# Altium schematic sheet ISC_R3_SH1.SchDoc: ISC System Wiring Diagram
size B; DrawnBy: Filiberto Clara; Engineer: Filiberto Clara; Organization: LIGO Laboratory; Address1: California Institute of Technology; Address2: Massachusetts Institute of Technology; SheetNumber: 17; SheetTotal: 39
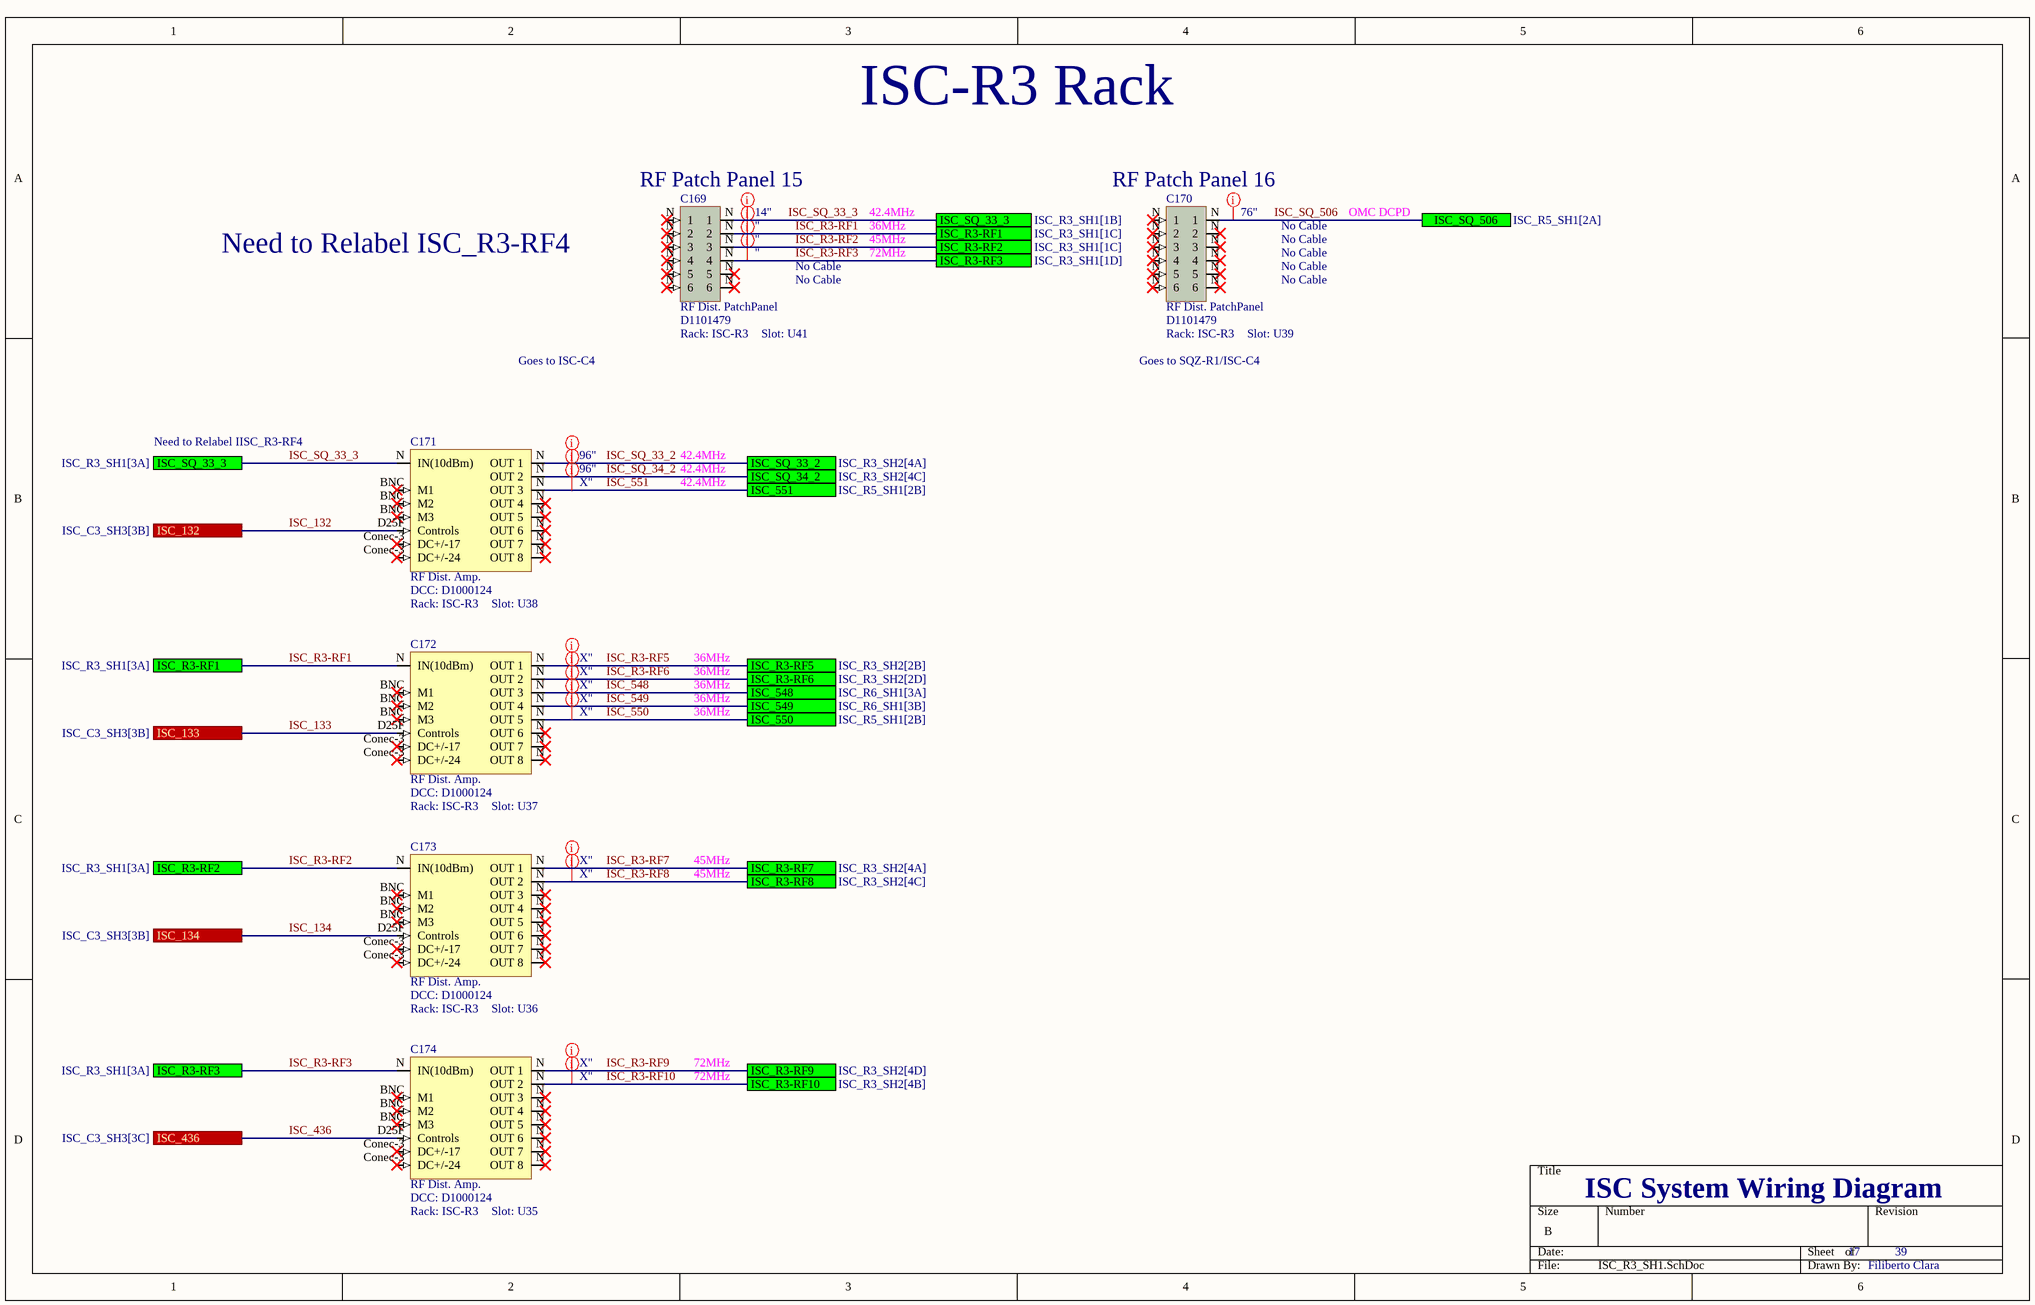
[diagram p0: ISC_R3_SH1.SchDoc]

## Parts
C169  RF Dist. PatchPanel  DCC: D1101479  Rack: ISC-R3  Slot: U41
C170  RF Dist. PatchPanel  DCC: D1101479  Rack: ISC-R3  Slot: U39
C171  RF Dist. Amp.  DCC: D1000124  Rack: ISC-R3  Slot: U38
C172  RF Dist. Amp.  DCC: D1000124  Rack: ISC-R3  Slot: U37
C173  RF Dist. Amp.  DCC: D1000124  Rack: ISC-R3  Slot: U36
C174  RF Dist. Amp.  DCC: D1000124  Rack: ISC-R3  Slot: U35

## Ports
ISC_132 (see ISC_C3_SH3[3B]), ISC_133 (see ISC_C3_SH3[3B]), ISC_134 (see ISC_C3_SH3[3B]), ISC_436 (see ISC_C3_SH3[3C]), ISC_548 (see ISC_R6_SH1[3A]), ISC_549 (see ISC_R6_SH1[3B]), ISC_550 (see ISC_R5_SH1[2B]), ISC_551 (see ISC_R5_SH1[2B]), ISC_R3-RF1 (see ISC_R3_SH1[1C]), ISC_R3-RF1 (see ISC_R3_SH1[3A]), ISC_R3-RF2 (see ISC_R3_SH1[1C]), ISC_R3-RF2 (see ISC_R3_SH1[3A]), ISC_R3-RF3 (see ISC_R3_SH1[1D]), ISC_R3-RF3 (see ISC_R3_SH1[3A]), ISC_R3-RF5 (see ISC_R3_SH2[2B]), ISC_R3-RF6 (see ISC_R3_SH2[2D]), ISC_R3-RF7 (see ISC_R3_SH2[4A]), ISC_R3-RF8 (see ISC_R3_SH2[4C]), ISC_R3-RF9 (see ISC_R3_SH2[4D]), ISC_R3-RF10 (see ISC_R3_SH2[4B]), ISC_SQ_33_2 (see ISC_R3_SH2[4A]), ISC_SQ_33_3 (see ISC_R3_SH1[1B]), ISC_SQ_33_3 (see ISC_R3_SH1[3A]), ISC_SQ_34_2 (see ISC_R3_SH2[4C]), ISC_SQ_506 (see ISC_R5_SH1[2A])

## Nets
ISC_132: C171.D25F(Controls) ; port ISC_132
ISC_133: C172.D25F(Controls) ; port ISC_133
ISC_134: C173.D25F(Controls) ; port ISC_134
ISC_436: C174.D25F(Controls) ; port ISC_436
ISC_548: C172.N(OUT_3) ; port ISC_548
ISC_549: C172.N(OUT_4) ; port ISC_549
ISC_550: C172.N(OUT_5) ; port ISC_550
ISC_551: C171.N(OUT_3) ; port ISC_551
ISC_R3-RF1: C169.N(2) C172.N(IN(10dBm)) ; port ISC_R3-RF1
ISC_R3-RF2: C169.N(3) C173.N(IN(10dBm)) ; port ISC_R3-RF2
ISC_R3-RF3: C169.N(4) C174.N(IN(10dBm)) ; port ISC_R3-RF3
ISC_R3-RF5: C172.N(OUT_1) ; port ISC_R3-RF5
ISC_R3-RF6: C172.N(OUT_2) ; port ISC_R3-RF6
ISC_R3-RF7: C173.N(OUT_1) ; port ISC_R3-RF7
ISC_R3-RF8: C173.N(OUT_2) ; port ISC_R3-RF8
ISC_R3-RF9: C174.N(OUT_1) ; port ISC_R3-RF9
ISC_R3-RF10: C174.N(OUT_2) ; port ISC_R3-RF10
ISC_SQ_33_2: C171.N(OUT_1) ; port ISC_SQ_33_2
ISC_SQ_33_3: C169.N(1) C171.N(IN(10dBm)) ; port ISC_SQ_33_3
ISC_SQ_34_2: C171.N(OUT_2) ; port ISC_SQ_34_2
ISC_SQ_506: C170.N(1) ; port ISC_SQ_506

Not connected (* = marked no-connect by the designer): C171 BNC(M1)* Conec-3(DC+/-17)*; C172 BNC(M1)* Conec-3(DC+/-17)*; C173 BNC(M1)* Conec-3(DC+/-17)*; C174 BNC(M1)* Conec-3(DC+/-17)*

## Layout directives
Length: ": ISC_R3-RF1, ISC_R3-RF2, ISC_R3-RF3
Length: 96": ISC_SQ_33_2, ISC_SQ_34_2
Length: X": ISC_548, ISC_549, ISC_550, ISC_551, ISC_R3-RF5, ISC_R3-RF6, ISC_R3-RF7, ISC_R3-RF8, ISC_R3-RF9, ISC_R3-RF10
Length: 14": ISC_SQ_33_3
Length: 76": ISC_SQ_506

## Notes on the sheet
- ISC-R3 Rack
- (near C169) RF Patch Panel 15
- 36MHz
- 45MHz
- 42.4MHz
- (near C170) RF Patch Panel 16
- No Cable
- OMC DCPD
- Need to Relabel ISC_R3-RF4
- 72MHz
- Goes to ISC-C4
- Goes to SQZ-R1/ISC-C4
- Need to Relabel IISC_R3-RF4

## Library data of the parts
C169 C170 = RF Dist. PatchPanel: Serial: Sxxxxxxx; System: ISC
C171-C174 = RF Distribution Amplifier: Serial: Sxxxxxxx; System: ISC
